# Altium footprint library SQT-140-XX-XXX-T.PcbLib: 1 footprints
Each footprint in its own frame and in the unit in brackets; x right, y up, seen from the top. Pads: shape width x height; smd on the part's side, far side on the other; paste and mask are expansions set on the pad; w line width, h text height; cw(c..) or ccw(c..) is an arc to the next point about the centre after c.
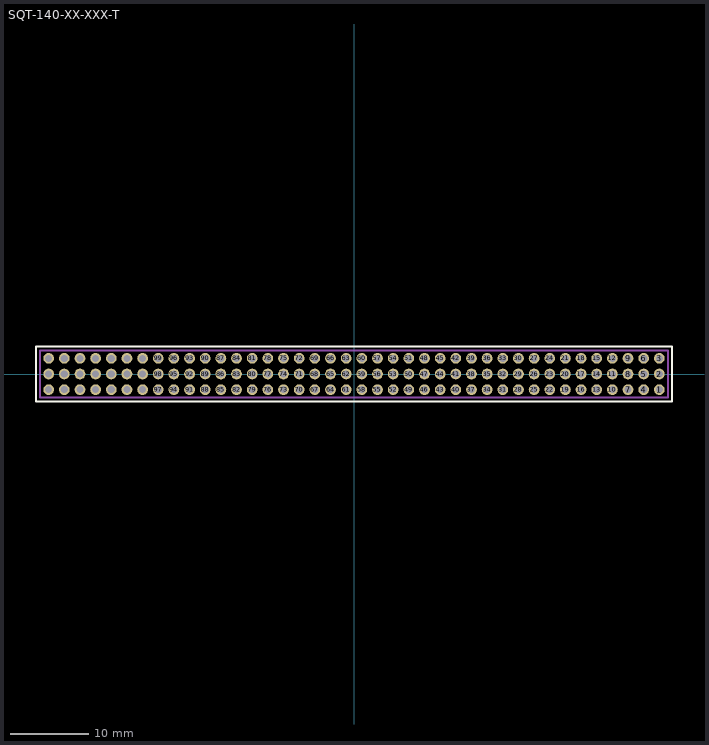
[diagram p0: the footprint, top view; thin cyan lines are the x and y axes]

## SQT-140-XX-XXX-T [mil]
pads (120):
  round 54 hole 36 mask+3: 1(1535.43,-78.74) 2(1535.43,0) 3(1535.43,78.74) 4(1456.69,-78.74) 5(1456.69,0) 6(1456.69,78.74) 7(1377.95,-78.74) 8(1377.95,0) 9(1377.95,78.74) 10(1299.21,-78.74) 11(1299.21,0) 12(1299.21,78.74) 13(1220.47,-78.74) 14(1220.47,0) 15(1220.47,78.74) 16(1141.73,-78.74) 17(1141.73,0) 18(1141.73,78.74) 19(1062.99,-78.74) 20(1062.99,0) 21(1062.99,78.74) 22(984.25,-78.74) 23(984.25,0) 24(984.25,78.74) 25(905.51,-78.74) 26(905.51,0) 27(905.51,78.74) 28(826.77,-78.74) 29(826.77,0) 30(826.77,78.74) 31(748.03,-78.74) 32(748.03,0) 33(748.03,78.74) 34(669.29,-78.74) 35(669.29,0) 36(669.29,78.74) 37(590.55,-78.74) 38(590.55,0) 39(590.55,78.74) 40(511.81,-78.74) 41(511.81,0) 42(511.81,78.74) 43(433.07,-78.74) 44(433.07,0) 45(433.07,78.74) 46(354.33,-78.74) 47(354.33,0) 48(354.33,78.74) 49(275.59,-78.74) 50(275.59,0) 51(275.59,78.74) 52(196.85,-78.74) 53(196.85,0) 54(196.85,78.74) 55(118.11,-78.74) 56(118.11,0) 57(118.11,78.74) 58(39.37,-78.74) 59(39.37,0) 60(39.37,78.74) 61(-39.37,-78.74) 62(-39.37,0) 63(-39.37,78.74) 64(-118.11,-78.74) 65(-118.11,0) 66(-118.11,78.74) 67(-196.85,-78.74) 68(-196.85,0) 69(-196.85,78.74) 70(-275.59,-78.74) 71(-275.59,0) 72(-275.59,78.74) 73(-354.33,-78.74) 74(-354.33,0) 75(-354.33,78.74) 76(-433.07,-78.74) 77(-433.07,0) 78(-433.07,78.74) 79(-511.81,-78.74) 80(-511.81,0) 81(-511.81,78.74) 82(-590.55,-78.74) 83(-590.55,0) 84(-590.55,78.74) 85(-669.29,-78.74) 86(-669.29,0) 87(-669.29,78.74) 88(-748.03,-78.74) 89(-748.03,0) 90(-748.03,78.74) 91(-826.77,-78.74) 92(-826.77,0) 93(-826.77,78.74) 94(-905.51,-78.74) 95(-905.51,0) 96(-905.51,78.74) 97(-984.25,-78.74) 98(-984.25,0) 99(-984.25,78.74) 100(-1062.99,-78.74) 101(-1062.99,0) 102(-1062.99,78.74) 103(-1141.73,-78.74) 104(-1141.73,0) 105(-1141.73,78.74) 106(-1220.47,-78.74) 107(-1220.47,0) 108(-1220.47,78.74) 109(-1299.21,-78.74) 110(-1299.21,0) 111(-1299.21,78.74) 112(-1377.95,-78.74) 113(-1377.95,0) 114(-1377.95,78.74) 115(-1456.69,-78.74) 116(-1456.69,0) 117(-1456.69,78.74) 118(-1535.43,-78.74) 119(-1535.43,0) 120(-1535.43,78.74)
Top Overlay:
  lines w10: -1599.85,-138.1 -1599.85,138.1 1599.85,138.1 1599.85,-138.1 -1599.85,-138.1
Mechanical 1:
  lines w10: -1579.85,-118.1 -1579.85,118.1 1579.85,118.1 1579.85,-118.1 -1579.85,-118.1
  text "J1" at -17.57,-183 h30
